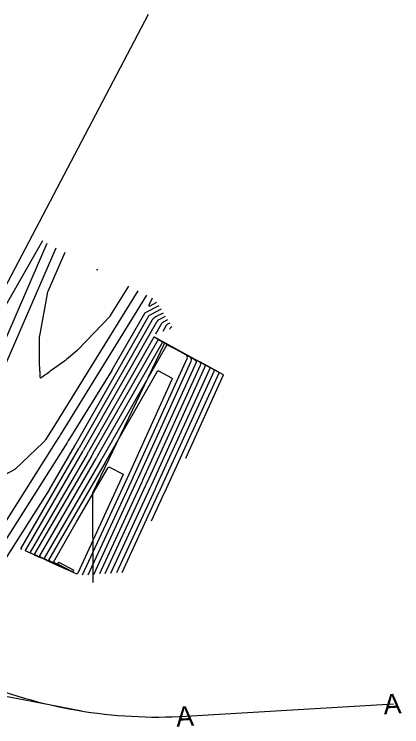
# Model space of a CAD drawing. Extents: x 688474 to 694748, y 765018 to 767373.
# Drawn here: x 688960.5 to 689193.1, y 766944.7 to 767372.6 of the extents above; entities that cross this region are included whole.
import ezdxf

# ---------------------------------------------------------------- set-up
doc = ezdxf.new("R2010")
doc.units = 0
for name, color, linetype in [('Default', 7, 'Continuous'), ('Prop_Contours_Major', 7, 'Continuous'), ('Prop_Contours_Minor', 7, 'Continuous'), ('R_Draft', 7, 'Continuous'), ('R_Horz Alg', 7, 'Continuous')]:
    doc.layers.add(name, color=color, linetype=linetype)

msp = doc.modelspace()

# ---------------------------------------------------------------- linework, layer by layer
at = {"layer": 'Default'}
msp.add_lwpolyline([(689001.05, 766954.08), (688971.09, 766959.79), (688865.78, 766979.87)], dxfattribs=at)
at = {"layer": 'Prop_Contours_Major'}
for points in [[(689047.39, 767197.5), (689039.03, 767193.23), (689038.9, 767193.15), (689038.79, 767193.06), (689038.69, 767192.95), (689038.61, 767192.83), (689019.15, 767158.76), (689019.13, 767158.72), (689019.11, 767158.68), (689019.08, 767158.64), (689019.06, 767158.6), (688992.96, 767116.36), (688992.75, 767116.03), (688992.55, 767115.71), (688992.35, 767115.38), (688992.14, 767115.06), (688910.76, 766986.88)], [(689053.96, 767187.09), (689052.52, 767186.36), (689052.29, 767186.22), (689052.09, 767186.06), (689051.91, 767185.87), (689051.77, 767185.64), (689049.74, 767182.09)], [(688981.36, 767043.84), (688976.78, 767046.03), (688976.55, 767046.14), (688976.32, 767046.25), (688976.1, 767046.36), (688975.88, 767046.48), (688973.07, 767047.95), (688972.94, 767048.04), (688972.88, 767048.15), (688972.87, 767048.28), (688972.93, 767048.43), (689006.78, 767106.87), (689007.08, 767107.39), (689007.38, 767107.91), (689007.68, 767108.43), (689007.98, 767108.96), (689046.89, 767177.1), (689046.92, 767177.14), (689046.95, 767177.16), (689046.99, 767177.16), (689047.04, 767177.14), (689049.86, 767175.66), (689050.07, 767175.55), (689050.28, 767175.44), (689050.48, 767175.33), (689050.69, 767175.21), (689068.74, 767165.28), (689069.33, 767164.84), (689069.65, 767164.31), (689069.71, 767163.69), (689069.5, 767162.99), (689037.79, 767093.15), (689037.57, 767092.65), (689037.34, 767092.16), (689037.12, 767091.66), (689036.89, 767091.17), (689011.63, 767036.42)], [(689071.68, 767163.99), (689083.05, 767157.73), (689083.22, 767157.6), (689083.31, 767157.45), (689083.33, 767157.28), (689083.27, 767157.08), (689050.67, 767085.28), (689050.64, 767085.23), (689050.62, 767085.18), (689050.6, 767085.13), (689050.57, 767085.07), (689042.8, 767068.23)]]:
    msp.add_lwpolyline(points, dxfattribs=at)
msp.add_lwpolyline([(688995.57, 767037.73), (688995.56, 767037.74), (688995.54, 767037.74), (688986.74, 767042.37), (688986.74, 767042.37), (688987.29, 767043.31), (688987.35, 767043.39), (688987.41, 767043.42), (688987.49, 767043.43), (688987.58, 767043.4), (688995.96, 767038.99), (688996.08, 767038.91), (688996.14, 767038.81), (688996.15, 767038.69), (688996.11, 767038.55), (688995.72, 767037.7), (688995.71, 767037.68), (688995.7, 767037.68), (688995.69, 767037.68), (688995.67, 767037.68), (688995.61, 767037.71), (688995.59, 767037.72)], close=True, dxfattribs=at)
at = {"layer": 'Prop_Contours_Minor'}
for points in [[(688977.56, 767236.57), (688927.77, 767149.88), (688927.74, 767149.84), (688927.72, 767149.79), (688927.69, 767149.75), (688927.67, 767149.71), (688919.39, 767135.42)], [(688940.46, 767143.43), (688980.27, 767235.14)], [(688946.26, 767141.76), (688985.58, 767232.35)], [(688990.89, 767229.56), (688980.67, 767206.01), (688980.55, 767205.7), (688980.44, 767205.39), (688980.35, 767205.08), (688980.29, 767204.75), (688975.61, 767179.42), (688975.57, 767179.17), (688975.54, 767178.91), (688975.52, 767178.65), (688975.51, 767178.4), (688975.44, 767166.03), (688975.44, 767165.38), (688975.45, 767164.74), (688975.47, 767164.1), (688975.5, 767163.46), (688975.74, 767158.8), (688975.75, 767158.61), (688975.75, 767158.43), (688975.76, 767158.25), (688975.76, 767158.06), (688975.77, 767157.33), (688975.77, 767157.14), (688975.78, 767156.96), (688975.79, 767156.77), (688975.8, 767156.59), (688975.93, 767154.75), (688975.99, 767154.46), (688976.12, 767154.3), (688976.33, 767154.29), (688976.6, 767154.43), (688978.94, 767155.99), (688979.26, 767156.21), (688979.57, 767156.43), (688979.88, 767156.66), (688980.19, 767156.89), (688981.42, 767157.83), (688981.72, 767158.06), (688982.03, 767158.29), (688982.34, 767158.52), (688982.66, 767158.74), (688990.62, 767164.38), (688990.95, 767164.62), (688991.28, 767164.86), (688991.6, 767165.12), (688991.91, 767165.38), (688998.07, 767170.56), (688998.22, 767170.7), (688998.37, 767170.83), (688998.52, 767170.97), (688998.66, 767171.11), (689018.26, 767191.48), (689018.28, 767191.5), (689018.29, 767191.52), (689018.31, 767191.54), (689018.32, 767191.56), (689029.32, 767209.35)], [(689010.13, 767219.44), (689010.11, 767219), (689010.11, 767218.97), (689010.12, 767218.95), (689010.14, 767218.95), (689010.17, 767218.97), (689010.38, 767219.15), (689010.39, 767219.16), (689010.4, 767219.17), (689010.41, 767219.18), (689010.42, 767219.19), (689010.49, 767219.26)], [(689034.63, 767206.56), (688982.04, 767121.47), (688981.99, 767121.38), (688981.93, 767121.29), (688981.88, 767121.2), (688981.82, 767121.11), (688979.23, 767117.04), (688978.94, 767116.61), (688978.63, 767116.2), (688978.29, 767115.81), (688977.92, 767115.44), (688960.78, 767099.22), (688960.73, 767099.17), (688960.67, 767099.13), (688960.61, 767099.09), (688960.55, 767099.05), (688943.08, 767089.77)], [(689039.94, 767203.77), (688988.34, 767120.27), (688987.79, 767119.39), (688987.24, 767118.5), (688986.68, 767117.62), (688986.13, 767116.74), (688944.65, 767051.41)], [(689043.32, 767201.99), (689041.49, 767198.19), (689041.3, 767197.68), (689041.34, 767197.4), (689041.62, 767197.36), (689042.13, 767197.56), (689046.08, 767199.58)], [(689048.71, 767195.42), (689042.27, 767192.13), (689041.87, 767191.89), (689041.51, 767191.6), (689041.2, 767191.26), (689040.94, 767190.86), (688996.82, 767113.6), (688996.79, 767113.55), (688996.76, 767113.49), (688996.73, 767113.44), (688996.7, 767113.39), (688981.54, 767087.22), (688981.51, 767087.17), (688981.48, 767087.12), (688981.45, 767087.07), (688981.42, 767087.02), (688895.7, 766952.01)], [(688965.35, 767051.08), (688964.82, 767051.33), (688964.8, 767051.34), (688964.77, 767051.35), (688964.75, 767051.37), (688964.72, 767051.38), (688964.41, 767051.54), (688964.39, 767051.56), (688964.38, 767051.57), (688964.38, 767051.6), (688964.39, 767051.62), (688999.2, 767111.73), (688999.31, 767111.91), (688999.41, 767112.1), (688999.52, 767112.28), (688999.63, 767112.47), (689043.27, 767188.89), (689043.71, 767189.56), (689044.23, 767190.13), (689044.83, 767190.63), (689045.51, 767191.04), (689050.02, 767193.33)], [(688970.69, 767048.67), (688968.81, 767049.56), (688968.71, 767049.61), (688968.62, 767049.65), (688968.53, 767049.7), (688968.44, 767049.75), (688967.34, 767050.32), (688967.27, 767050.38), (688967.23, 767050.44), (688967.23, 767050.51), (688967.26, 767050.6), (689001.7, 767110.07), (689001.89, 767110.38), (689002.07, 767110.7), (689002.25, 767111.02), (689002.43, 767111.34), (689046.08, 767187.78), (689046.44, 767188.31), (689046.85, 767188.77), (689047.33, 767189.17), (689047.88, 767189.49), (689051.33, 767191.25)], [(689045.48, 767180.68), (689048.93, 767186.71), (689049.18, 767187.09), (689049.47, 767187.41), (689049.81, 767187.69), (689050.2, 767187.93), (689052.65, 767189.17)], [(689054, 767183.5), (689054.61, 767184.58), (689054.65, 767184.64), (689054.71, 767184.7), (689054.77, 767184.75), (689054.84, 767184.79), (689055.27, 767185.01)], [(689015.04, 767036.67), (689039.5, 767089.67), (689039.75, 767090.22), (689040, 767090.76), (689040.25, 767091.31), (689040.49, 767091.85), (689072.26, 767161.81), (689072.43, 767162.41), (689072.38, 767162.94), (689072.11, 767163.39), (689071.6, 767163.77), (689045.86, 767177.94), (689045.78, 767177.98), (689045.7, 767178.03), (689045.61, 767178.07), (689045.53, 767178.12), (689044.5, 767178.66), (689044.44, 767178.68), (689044.38, 767178.68), (689044.33, 767178.65), (689044.29, 767178.6), (689005.24, 767110.21), (689004.98, 767109.76), (689004.72, 767109.31), (689004.46, 767108.86), (689004.21, 767108.41), (688970.13, 767049.58), (688970.08, 767049.43), (688970.08, 767049.3), (688970.14, 767049.2), (688970.27, 767049.1), (688972.16, 767048.11), (688972.31, 767048.03), (688972.47, 767047.95), (688972.63, 767047.87), (688972.79, 767047.79), (688976.02, 767046.25)], [(689008.2, 767036.16), (689034.35, 767092.81), (689034.52, 767093.18), (689034.69, 767093.55), (689034.86, 767093.92), (689035.02, 767094.29), (689066.75, 767164.17), (689066.99, 767164.97), (689066.92, 767165.68), (689066.55, 767166.28), (689065.88, 767166.79), (689055.52, 767172.49), (689055.19, 767172.67), (689054.86, 767172.85), (689054.53, 767173.03), (689054.19, 767173.2), (689049.58, 767175.63), (689049.55, 767175.64), (689049.53, 767175.64), (689049.5, 767175.62), (689049.48, 767175.6), (689010.48, 767107.3), (689010.26, 767106.91), (689010.03, 767106.51), (689009.81, 767106.12), (689009.58, 767105.73), (688975.69, 767047.22), (688975.65, 767047.1), (688975.65, 767047), (688975.7, 767046.91), (688975.8, 767046.84), (688979.59, 767044.84), (688979.88, 767044.69), (688980.17, 767044.55), (688980.47, 767044.4), (688980.76, 767044.26), (688986.69, 767041.43)], [(689018.45, 767036.9), (689042.27, 767088.52), (689042.46, 767088.94), (689042.65, 767089.37), (689042.85, 767089.79), (689043.04, 767090.21), (689075.01, 767160.63), (689075.16, 767161.13), (689075.12, 767161.57), (689074.89, 767161.94), (689074.47, 767162.26), (689045.59, 767178.16)], [(689004.78, 767035.89), (689031.81, 767094.46), (689031.92, 767094.7), (689032.03, 767094.95), (689032.14, 767095.19), (689032.26, 767095.44), (689064.23, 767165.87), (689064.43, 767166.53), (689064.37, 767167.11), (689064.07, 767167.61), (689063.51, 767168.02), (689060.35, 767169.76), (689059.9, 767170.01), (689059.44, 767170.26), (689058.98, 767170.5), (689058.52, 767170.75), (689052.12, 767174.11), (689052.11, 767174.12), (689052.1, 767174.12), (689052.09, 767174.11), (689052.08, 767174.1), (689012.99, 767105.64), (689012.84, 767105.38), (689012.69, 767105.12), (689012.54, 767104.86), (689012.39, 767104.6), (688978.46, 767046), (688978.42, 767045.92), (688978.42, 767045.84), (688978.46, 767045.77), (688978.54, 767045.72), (688983.31, 767043.21), (688983.67, 767043.02), (688984.03, 767042.84), (688984.38, 767042.67), (688984.75, 767042.49), (688992.03, 767039.02)], [(689054.29, 767173.43), (689077.33, 767160.75), (689077.66, 767160.5), (689077.85, 767160.2), (689077.88, 767159.85), (689077.76, 767159.44), (689045.58, 767088.56), (689045.44, 767088.27), (689045.31, 767087.97), (689045.17, 767087.67), (689045.04, 767087.37), (689021.85, 767037.13)], [(689025.26, 767037.36), (689047.8, 767086.22), (689047.88, 767086.4), (689047.96, 767086.57), (689048.04, 767086.75), (689048.12, 767086.92), (689080.51, 767158.26), (689080.6, 767158.56), (689080.58, 767158.82), (689080.44, 767159.05), (689080.19, 767159.24), (689062.98, 767168.71)], [(688997.36, 767036.61), (688988.73, 767040.72), (688988.3, 767040.93), (688987.88, 767041.14), (688987.45, 767041.36), (688987.03, 767041.58), (688981.27, 767044.6), (688981.22, 767044.64), (688981.2, 767044.68), (688981.2, 767044.73), (688981.22, 767044.79), (689015.2, 767103.47), (689015.27, 767103.59), (689015.35, 767103.72), (689015.42, 767103.85), (689015.49, 767103.98), (689046.47, 767158.23), (689046.58, 767158.37), (689046.7, 767158.44), (689046.85, 767158.45), (689047.01, 767158.39), (689054.83, 767154.27), (689055.11, 767154.07), (689055.27, 767153.83), (689055.29, 767153.54), (689055.2, 767153.21), (689029.49, 767096.59), (689029.43, 767096.47), (689029.38, 767096.35), (689029.32, 767096.22), (689029.27, 767096.1), (689001.36, 767035.63)], [(689080.38, 767159.26), (689085.92, 767156.22), (689086, 767156.16), (689086.04, 767156.08), (689086.05, 767156), (689086.02, 767155.9), (689063.29, 767105.84)]]:
    msp.add_lwpolyline(points, dxfattribs=at)
msp.add_lwpolyline([(688997.94, 767067.68), (689016.67, 767100.03), (689016.96, 767100.4), (689017.3, 767100.59), (689017.69, 767100.61), (689018.13, 767100.45), (689025.87, 767096.38), (689025.95, 767096.33), (689025.99, 767096.27), (689025.99, 767096.19), (689025.97, 767096.11), (688998.66, 767036.92), (688998.49, 767036.65), (688998.27, 767036.51), (688998.01, 767036.48), (688997.71, 767036.58), (688992.71, 767038.96), (688992.22, 767039.2), (688991.73, 767039.44), (688991.24, 767039.69), (688990.75, 767039.94), (688984.01, 767043.49), (688983.98, 767043.5), (688983.97, 767043.53), (688983.97, 767043.55), (688983.98, 767043.58)], close=True, dxfattribs=at)
at = {"layer": 'R_Draft'}
msp.add_lwpolyline([(689007.87, 767031.27), (689007.59, 767085.2), (689050.62, 767174.77)], dxfattribs=at)
at = {"layer": 'R_Horz Alg'}
for p, q in [((688836.45, 766983.16), (689041.19, 767372.58)), ((689063.59, 766951.01), (689188.13, 766958.45))]:
    msp.add_line(p, q, dxfattribs=at)
msp.add_arc((689046.52, 767236.98), 286.48, 247.2665, 273.4162, dxfattribs=at)

# ---------------------------------------------------------------- texts
for p in [(689182.49, 766952.1), (689057.96, 766944.67)]:
    msp.add_text('A', height=12, rotation=3.4162, dxfattribs=at).set_placement(p)

doc.saveas('drawing.dxf')
